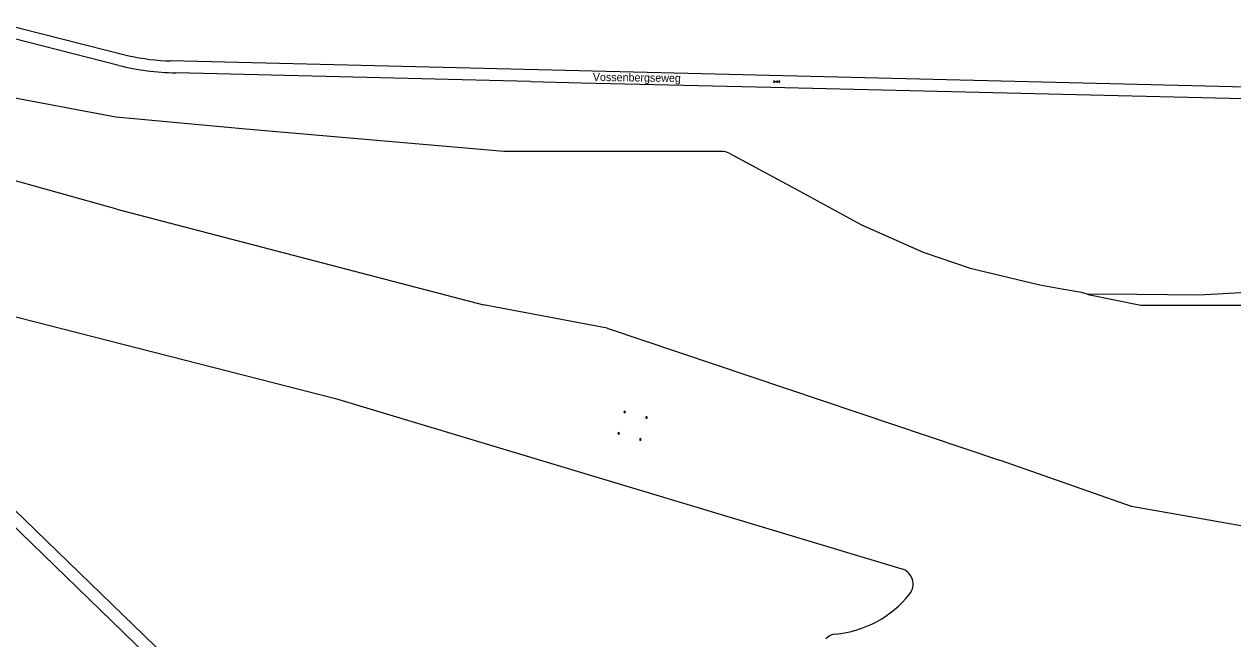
# Model space of a CAD drawing. Extents: x 130998 to 133001, y 398999 to 403002.
# Drawn here: x 132162 to 132539.6, y 400959.6 to 401151.4 of the extents above; entities that cross this region are included whole.
import ezdxf

# ---------------------------------------------------------------- set-up
doc = ezdxf.new("R2010")
doc.units = 0
for name, color, linetype in [('gg-anno-openbare ruimte label', 7, 'Continuous'), ('gg-bbg-hoogspanningsmast', 7, 'Continuous'), ('gg-knt-onverhard', 7, 'Continuous'), ('gg-knt-verharding', 7, 'Continuous'), ('gg-kntw-bovenkant insteek waterloop', 7, 'Continuous'), ('gt-grn-groengrens', 7, 'Continuous'), ('gt-symb-gesloten verharding', 7, 'Continuous')]:
    doc.layers.add(name, color=color, linetype=linetype)

# ---------------------------------------------------------------- blocks, each defined once
blk = doc.blocks.new('gt0-GESVH1')
at = {"layer": 'gt-symb-gesloten verharding'}
for p, q in [((-0.99, -0.26), (0.01, 0.24)), ((0.01, -0.26), (-0.99, 0.24)), ((0.01, 0.24), (1.01, -0.26)), ((1.01, 0.24), (0.01, -0.26))]:
    blk.add_line(p, q, dxfattribs=at)

msp = doc.modelspace()

# ---------------------------------------------------------------- linework, layer by layer
at = {"layer": 'gg-bbg-hoogspanningsmast'}
for centre, start, end in [((132349.63, 401030.37), 0.3472, 180.3472), ((132349.63, 401030.37), 180.3472, 0.3472), ((132356.44, 401028.65), 359.8843, 180.1157), ((132356.44, 401028.65), 180.1157, 359.8843), ((132347.77, 401023.69), 0.3472, 180.3472), ((132347.77, 401023.69), 180.3472, 0.3472), ((132354.54, 401021.8), 0, 180), ((132354.54, 401021.8), 180, 0)]:
    msp.add_arc(centre, 0.248, start, end, dxfattribs=at)
at = {"layer": 'gg-knt-onverhard'}
msp.add_line((132153.31, 401000), (132235.64, 400920.27), dxfattribs=at)
msp.add_lwpolyline([(132158.77, 401000), (132325.87, 400838.2), (132339.76, 400823.47), (132347.87, 400813.94)], dxfattribs=at)
at = {"layer": 'gg-knt-verharding'}
for p, q in [((132000, 401190.85), (132194.73, 401141.61)), ((132191.63, 401138.57), (132000, 401187.05)), ((132607.9, 401130.28), (132207.77, 401139.97)), ((132320.16, 401133.55), (132209.35, 401136.29)), ((132320.16, 401133.55), (132336.1, 401133.18))]:
    msp.add_line(p, q, dxfattribs=at)
msp.add_lwpolyline([(132336.1, 401133.18), (132395.28, 401131.81), (132608.05, 401126.64)], dxfattribs=at)
for centre, radius, start, end in [((132209.79, 401208.53), 68.6, 257.3166, 268.31), ((132210.18, 401212.51), 76.23, 255.9157, 269.3703)]:
    msp.add_arc(centre, radius, start, end, dxfattribs=at)
at = {"layer": 'gg-kntw-bovenkant insteek waterloop'}
msp.add_line((132494.46, 401067.05), (132510.87, 401063.75), dxfattribs=at)
for points in [[(132510.87, 401063.75), (132544.02, 401063.7), (132574.52, 401066.33), (132605.67, 401069.13), (132612.23, 401069.44)], [(132543.8, 401067.67), (132534.88, 401067.12), (132528.94, 401066.81), (132500, 401067.13), (132494.46, 401067.05)]]:
    msp.add_lwpolyline(points, dxfattribs=at)
at = {"layer": 'gt-grn-groengrens'}
for p, q in [((132190.92, 401093.7), (132111.87, 401115.66)), ((132190.92, 401093.7), (132305.5, 401063.87)), ((132344.19, 401056.53), (132305.5, 401063.87)), ((132344.19, 401056.53), (132467.01, 401015.19)), ((132507.96, 401000.91), (132467.01, 401015.19)), ((132613.71, 400982.06), (132507.96, 401000.91))]:
    msp.add_line(p, q, dxfattribs=at)
for points in [[(132190.7, 401122.43), (132149.63, 401130.14), (132102.24, 401135.75)], [(132379.93, 401111.75), (132311.92, 401111.75), (132231.29, 401118.62), (132190.7, 401122.43)], [(132382.3, 401111.16), (132404.18, 401099.39), (132423.6, 401088.8), (132442.9, 401080.31), (132457.59, 401075.25), (132479.35, 401070.1), (132486.23, 401068.81), (132492.36, 401067.74), (132494.01, 401067.24), (132494.46, 401067.05)], [(132150.39, 401062.4), (132259.31, 401034.59), (132436.18, 400981.44)]]:
    msp.add_lwpolyline(points, dxfattribs=at)
for centre, radius, start, end in [((132379.93, 401106.74), 5.01, 61.7414, 89.97), ((132434.74, 400976.65), 5, 321.4518, 73.2653), ((132412.35, 400994.49), 33.63, 275.3884, 321.4432), ((132415.98, 400956.04), 5, 95.3836, 135.0887)]:
    msp.add_arc(centre, radius, start, end, dxfattribs=at)

# ---------------------------------------------------------------- block references
at = {"layer": 'gt-symb-gesloten verharding', "rotation": -0.5729386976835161}
msp.add_blockref('gt0-GESVH1', (132397.14, 401133.51), dxfattribs=at)

# ---------------------------------------------------------------- texts
at = {"layer": 'gg-anno-openbare ruimte label'}
msp.add_text('Vossenbergseweg', height=2.5, rotation=359.3, dxfattribs=at).set_placement((132339.67, 401133.72))

doc.saveas('drawing.dxf')
